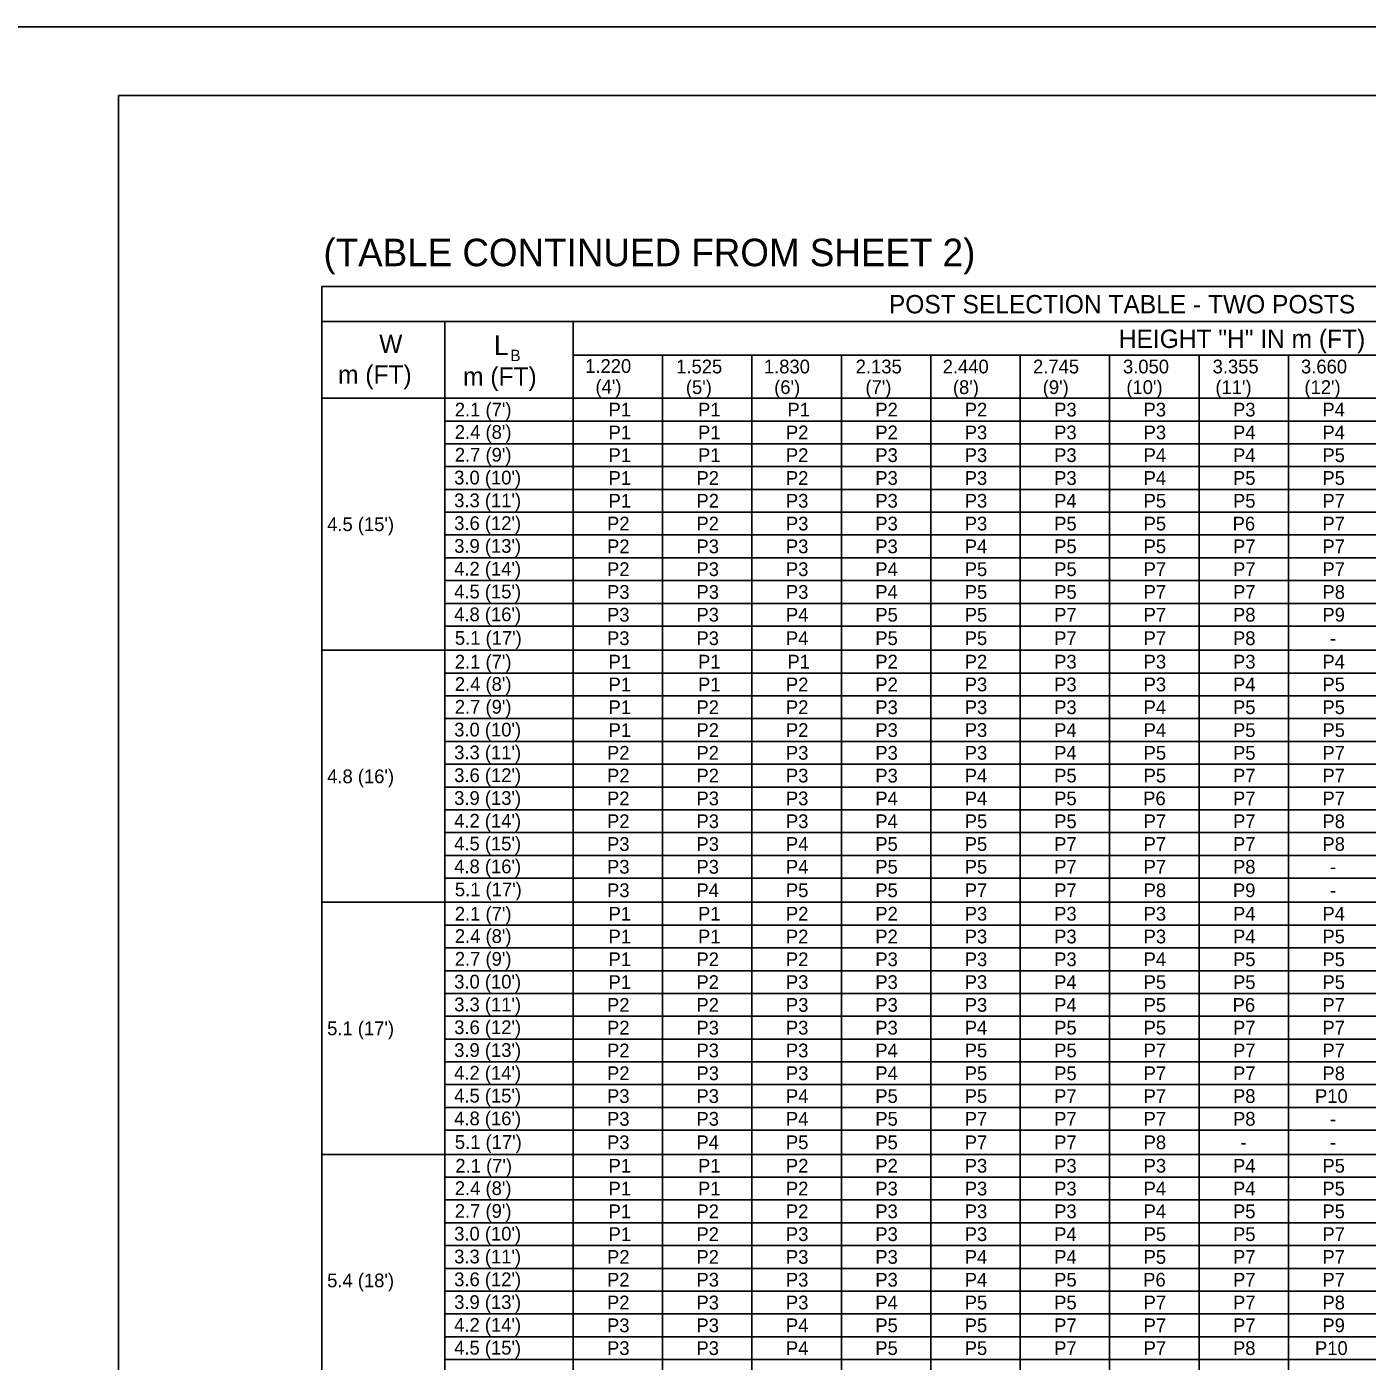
# Model space of a CAD drawing. Extents: x 637580 to 641008, y 294594 to 295782.
# Drawn here: x 639282.3 to 639574.7, y 295490.5 to 295781.6 of the extents above; entities that cross this region are included whole.
import ezdxf

# ---------------------------------------------------------------- set-up
doc = ezdxf.new("R2010")
doc.units = 0
for name, color, linetype in [('1', 7, 'Continuous'), ('2', 7, 'Continuous'), ('3', 7, 'Continuous'), ('PLT-BNDY', 7, 'Continuous')]:
    doc.layers.add(name, color=color, linetype=linetype)

msp = doc.modelspace()

# ---------------------------------------------------------------- linework, layer by layer
at = {"layer": '1'}
for p, q in [((639302.31, 295766.63), (640088.31, 295766.63)), ((639302.31, 295766.63), (639302.31, 295202.63)), ((639346.67, 295724.98), (639713.6, 295724.98)), ((639346.67, 295260.68), (639346.67, 295724.98)), ((639346.67, 295717.3), (639713.6, 295717.3)), ((639373.47, 295260.68), (639373.47, 295717.3)), ((639401.48, 295260.68), (639401.48, 295717.3)), ((639346.67, 295700.6), (639713.6, 295700.6)), ((639346.67, 295645.61), (639713.6, 295645.61)), ((639346.67, 295590.62), (639713.6, 295590.62)), ((639346.67, 295535.63), (639713.6, 295535.63))]:
    msp.add_line(p, q, dxfattribs=at)
at = {"layer": '2'}
for p, q in [((639401.48, 295260.68), (639401.48, 295717.3)), ((639401.48, 295709.96), (639713.6, 295709.96)), ((639420.98, 295260.68), (639420.98, 295709.96)), ((639440.49, 295260.68), (639440.49, 295709.96)), ((639460, 295260.68), (639460, 295709.96)), ((639479.51, 295260.68), (639479.51, 295709.96)), ((639499.01, 295260.68), (639499.01, 295709.96)), ((639518.52, 295260.68), (639518.52, 295709.96)), ((639538.03, 295260.68), (639538.03, 295709.96)), ((639557.54, 295260.68), (639557.54, 295709.96)), ((639373.47, 295695.62), (639713.6, 295695.62)), ((639373.47, 295690.65), (639713.6, 295690.65)), ((639373.47, 295685.68), (639713.6, 295685.68)), ((639373.47, 295680.71), (639713.6, 295680.71)), ((639373.47, 295675.73), (639713.6, 295675.73)), ((639373.47, 295670.76), (639713.6, 295670.76)), ((639373.47, 295665.79), (639713.6, 295665.79)), ((639373.47, 295660.82), (639713.6, 295660.82)), ((639373.47, 295655.84), (639713.6, 295655.84)), ((639373.47, 295650.87), (639713.6, 295650.87)), ((639373.47, 295640.63), (639713.6, 295640.63)), ((639373.47, 295635.66), (639713.6, 295635.66)), ((639373.47, 295630.69), (639713.6, 295630.69)), ((639373.47, 295625.72), (639713.6, 295625.72)), ((639373.47, 295620.74), (639713.6, 295620.74)), ((639373.47, 295615.77), (639713.6, 295615.77)), ((639373.47, 295610.8), (639713.6, 295610.8)), ((639373.47, 295605.83), (639713.6, 295605.83)), ((639373.47, 295600.85), (639713.6, 295600.85)), ((639373.47, 295595.88), (639713.6, 295595.88)), ((639373.47, 295585.64), (639713.6, 295585.64)), ((639373.47, 295580.67), (639713.6, 295580.67)), ((639373.47, 295575.7), (639713.6, 295575.7)), ((639373.47, 295570.73), (639713.6, 295570.73)), ((639373.47, 295565.75), (639713.6, 295565.75)), ((639373.47, 295560.78), (639713.6, 295560.78)), ((639373.47, 295555.81), (639713.6, 295555.81)), ((639373.47, 295550.84), (639713.6, 295550.84)), ((639373.47, 295545.86), (639713.6, 295545.86)), ((639373.47, 295540.89), (639713.6, 295540.89)), ((639373.47, 295530.65), (639713.6, 295530.65)), ((639373.47, 295525.68), (639713.6, 295525.68)), ((639373.47, 295520.71), (639713.6, 295520.71)), ((639373.47, 295515.74), (639713.6, 295515.74)), ((639373.47, 295510.76), (639713.6, 295510.76)), ((639373.47, 295505.79), (639713.6, 295505.79)), ((639373.47, 295500.82), (639713.6, 295500.82)), ((639373.47, 295495.85), (639713.6, 295495.85)), ((639373.47, 295490.87), (639713.6, 295490.87))]:
    msp.add_line(p, q, dxfattribs=at)
at = {"layer": 'PLT-BNDY'}
msp.add_lwpolyline([(639262.31, 295781.63), (640103.31, 295781.63), (640103.31, 295187.63), (639262.31, 295187.63)], close=True, dxfattribs=at)

# ---------------------------------------------------------------- texts
at = {"layer": '1'}
for s, height, p in [('POST SELECTION TABLE - TWO POSTS', 4.003, (639470.37, 295719.11)), ('HEIGHT "H" IN m (FT)', 4.003, (639520.52, 295711.56)), ('W', 4, (639359.19, 295710.47)), ('L', 4.3, (639384.22, 295709.99)), ('B', 2.5, (639387.79, 295708.68)), ('m (FT)', 4.003, (639350.21, 295703.76)), ('m (FT)', 4.003, (639377.48, 295703.36)), ('1.220', 3, (639404.12, 295706.12)), ('1.525', 3, (639423.97, 295706.01)), ('1.830', 3, (639443.1, 295706.01)), ('2.135', 3, (639463.13, 295706.01)), ('2.440', 3, (639482.1, 295706.01)), ('2.745', 3, (639501.81, 295706.01)), ('3.050', 3, (639521.43, 295706.01)), ('3.355', 3, (639540.98, 295706.01)), ('3.660', 3, (639560.27, 295706.01)), ("(4')", 3, (639406.36, 295701.62)), ("(5')", 3, (639426.08, 295701.51)), ("(6')", 3, (639445.34, 295701.51)), ("(7')", 3, (639465.25, 295701.51)), ("(8')", 3, (639484.34, 295701.51)), ("(9')", 3, (639503.93, 295701.51)), ("(10')", 3, (639522.17, 295701.51)), ("(11')", 3, (639541.59, 295701.51)), ("(12')", 3, (639561.01, 295701.51)), ("2.1 (7')", 3, (639375.68, 295696.61)), ('P1', 3, (639409.22, 295696.61)), ('P1', 3, (639428.73, 295696.61)), ('P1', 3, (639448.24, 295696.61)), ('P2', 3, (639467.4, 295696.61)), ('P2', 3, (639486.91, 295696.61)), ('P3', 3, (639506.42, 295696.61)), ('P3', 3, (639525.92, 295696.61)), ('P3', 3, (639545.43, 295696.61)), ('P4', 3, (639564.94, 295696.61)), ("2.4 (8')", 3, (639375.68, 295691.73)), ('P1', 3, (639409.22, 295691.64)), ('P1', 3, (639428.73, 295691.64)), ('P2', 3, (639447.9, 295691.64)), ('P2', 3, (639467.4, 295691.64)), ('P3', 3, (639486.91, 295691.64)), ('P3', 3, (639506.42, 295691.64)), ('P3', 3, (639525.93, 295691.64)), ('P4', 3, (639545.43, 295691.64)), ('P4', 3, (639564.94, 295691.64)), ("2.7 (9')", 3, (639375.68, 295686.76)), ('P1', 3, (639409.22, 295686.67)), ('P1', 3, (639428.73, 295686.67)), ('P2', 3, (639447.9, 295686.67)), ('P3', 3, (639467.4, 295686.67)), ('P3', 3, (639486.91, 295686.67)), ('P3', 3, (639506.42, 295686.67)), ('P4', 3, (639525.93, 295686.67)), ('P4', 3, (639545.43, 295686.67)), ('P5', 3, (639564.94, 295686.67)), ("3.0 (10')", 3, (639375.54, 295681.79)), ('P1', 3, (639409.22, 295681.69)), ('P2', 3, (639428.39, 295681.69)), ('P2', 3, (639447.9, 295681.69)), ('P3', 3, (639467.4, 295681.69)), ('P3', 3, (639486.91, 295681.69)), ('P3', 3, (639506.42, 295681.69)), ('P4', 3, (639525.93, 295681.69)), ('P5', 3, (639545.43, 295681.69)), ('P5', 3, (639564.94, 295681.69)), ("3.3 (11')", 3, (639375.54, 295676.81)), ('P1', 3, (639409.22, 295676.72)), ('P2', 3, (639428.39, 295676.72)), ('P3', 3, (639447.9, 295676.72)), ('P3', 3, (639467.4, 295676.72)), ('P3', 3, (639486.91, 295676.72)), ('P4', 3, (639506.42, 295676.72)), ('P5', 3, (639525.93, 295676.72)), ('P5', 3, (639545.43, 295676.72)), ('P7', 3, (639564.94, 295676.72)), ("3.6 (12')", 3, (639375.54, 295671.84)), ('P2', 3, (639408.88, 295671.75)), ('P2', 3, (639428.39, 295671.75)), ('P3', 3, (639447.9, 295671.75)), ('P3', 3, (639467.4, 295671.75)), ('P3', 3, (639486.91, 295671.75)), ('P6', 3, (639545.35, 295671.75)), ("4.5 (15')", 3, (639347.83, 295671.6)), ('P5', 3, (639506.42, 295671.75)), ('P5', 3, (639525.93, 295671.75)), ('P7', 3, (639564.94, 295671.75)), ("3.9 (13')", 3, (639375.54, 295666.87)), ('P2', 3, (639408.88, 295666.78)), ('P3', 3, (639428.39, 295666.78)), ('P3', 3, (639447.9, 295666.78)), ('P3', 3, (639467.4, 295666.78)), ('P4', 3, (639486.91, 295666.78)), ('P5', 3, (639506.42, 295666.78)), ('P5', 3, (639525.93, 295666.78)), ('P7', 3, (639545.43, 295666.78)), ('P7', 3, (639564.94, 295666.78)), ("4.2 (14')", 3, (639375.54, 295661.9)), ('P2', 3, (639408.88, 295661.8)), ('P3', 3, (639428.39, 295661.8)), ('P3', 3, (639447.9, 295661.8)), ('P4', 3, (639467.4, 295661.8)), ('P5', 3, (639486.91, 295661.8)), ('P5', 3, (639506.42, 295661.8)), ('P7', 3, (639525.93, 295661.8)), ('P7', 3, (639545.43, 295661.8)), ('P7', 3, (639564.94, 295661.8)), ("4.5 (15')", 3, (639375.54, 295656.92)), ('P3', 3, (639408.88, 295656.83)), ('P3', 3, (639428.39, 295656.83)), ('P3', 3, (639447.9, 295656.83)), ('P4', 3, (639467.4, 295656.83)), ('P5', 3, (639486.91, 295656.83)), ('P5', 3, (639506.42, 295656.83)), ('P7', 3, (639525.93, 295656.83)), ('P7', 3, (639545.43, 295656.83)), ('P8', 3, (639564.94, 295656.83)), ("4.8 (16')", 3, (639375.54, 295651.95)), ('P3', 3, (639408.88, 295651.86)), ('P3', 3, (639428.39, 295651.86)), ('P4', 3, (639447.9, 295651.86)), ('P5', 3, (639467.4, 295651.86)), ('P5', 3, (639486.91, 295651.86)), ('P7', 3, (639506.42, 295651.86)), ('P7', 3, (639525.93, 295651.86)), ('P8', 3, (639545.43, 295651.86)), ('P9', 3, (639564.93, 295651.86)), ("5.1 (17')", 3, (639375.69, 295646.8)), ('P3', 3, (639408.88, 295646.74)), ('P3', 3, (639428.39, 295646.74)), ('P4', 3, (639447.9, 295646.74)), ('P5', 3, (639467.4, 295646.74)), ('P5', 3, (639486.91, 295646.74)), ('P7', 3, (639506.42, 295646.74)), ('P7', 3, (639525.93, 295646.74)), ('P8', 3, (639545.43, 295646.74)), ('-', 3, (639566.56, 295646.74)), ("2.1 (7')", 3, (639375.68, 295641.62)), ('P1', 3, (639409.22, 295641.62)), ('P1', 3, (639428.73, 295641.62)), ('P1', 3, (639448.24, 295641.62)), ('P2', 3, (639467.4, 295641.62)), ('P2', 3, (639486.91, 295641.62)), ('P3', 3, (639506.42, 295641.62)), ('P3', 3, (639525.93, 295641.62)), ('P3', 3, (639545.43, 295641.62)), ('P4', 3, (639564.94, 295641.62)), ("2.4 (8')", 3, (639375.68, 295636.74)), ('P2', 3, (639447.9, 295636.65)), ('P2', 3, (639467.4, 295636.65)), ('P3', 3, (639486.91, 295636.65)), ('P3', 3, (639506.42, 295636.65)), ('P3', 3, (639525.93, 295636.65)), ('P1', 3, (639409.22, 295636.65)), ('P1', 3, (639428.73, 295636.65)), ('P4', 3, (639545.43, 295636.65)), ('P5', 3, (639564.94, 295636.65)), ("2.7 (9')", 3, (639375.68, 295631.77)), ('P1', 3, (639409.22, 295631.68)), ('P2', 3, (639428.39, 295631.68)), ('P2', 3, (639447.9, 295631.68)), ('P3', 3, (639467.4, 295631.68)), ('P3', 3, (639486.91, 295631.68)), ('P3', 3, (639506.42, 295631.68)), ('P4', 3, (639525.93, 295631.68)), ('P5', 3, (639545.43, 295631.68)), ('P5', 3, (639564.94, 295631.68)), ("3.0 (10')", 3, (639375.54, 295626.8)), ('P1', 3, (639409.22, 295626.7)), ('P2', 3, (639428.39, 295626.7)), ('P2', 3, (639447.9, 295626.7)), ('P3', 3, (639467.4, 295626.7)), ('P3', 3, (639486.91, 295626.7)), ('P4', 3, (639506.42, 295626.7)), ('P4', 3, (639525.93, 295626.7)), ('P5', 3, (639545.43, 295626.7)), ('P5', 3, (639564.94, 295626.7)), ("3.3 (11')", 3, (639375.54, 295621.82)), ('P2', 3, (639408.88, 295621.73)), ('P2', 3, (639428.39, 295621.73)), ('P3', 3, (639447.9, 295621.73)), ('P3', 3, (639467.4, 295621.73)), ('P3', 3, (639486.91, 295621.73)), ('P4', 3, (639506.42, 295621.73)), ('P5', 3, (639525.93, 295621.73)), ('P5', 3, (639545.43, 295621.73)), ('P7', 3, (639564.94, 295621.73)), ("4.8 (16')", 3, (639347.83, 295616.61)), ("3.6 (12')", 3, (639375.54, 295616.85)), ('P2', 3, (639408.88, 295616.76)), ('P2', 3, (639428.39, 295616.76)), ('P3', 3, (639447.9, 295616.76)), ('P3', 3, (639467.4, 295616.76)), ('P4', 3, (639486.91, 295616.76)), ('P5', 3, (639506.42, 295616.76)), ('P5', 3, (639525.93, 295616.76)), ('P7', 3, (639545.43, 295616.76)), ('P7', 3, (639564.94, 295616.76)), ("3.9 (13')", 3, (639375.54, 295611.88)), ('P2', 3, (639408.88, 295611.79)), ('P3', 3, (639428.39, 295611.79)), ('P3', 3, (639447.9, 295611.79)), ('P4', 3, (639467.4, 295611.79)), ('P4', 3, (639486.91, 295611.79)), ('P5', 3, (639506.42, 295611.79)), ('P6', 3, (639525.84, 295611.79)), ('P7', 3, (639545.43, 295611.79)), ('P7', 3, (639564.94, 295611.79)), ("4.2 (14')", 3, (639375.54, 295606.91)), ('P2', 3, (639408.88, 295606.81)), ('P3', 3, (639428.39, 295606.81)), ('P3', 3, (639447.9, 295606.81)), ('P4', 3, (639467.4, 295606.81)), ('P5', 3, (639486.91, 295606.81)), ('P5', 3, (639506.42, 295606.81)), ('P7', 3, (639525.93, 295606.81)), ('P7', 3, (639545.43, 295606.81)), ('P8', 3, (639564.94, 295606.81)), ("4.5 (15')", 3, (639375.54, 295601.93)), ('P3', 3, (639408.88, 295601.84)), ('P3', 3, (639428.39, 295601.84)), ('P4', 3, (639447.9, 295601.84)), ('P5', 3, (639467.4, 295601.84)), ('P5', 3, (639486.91, 295601.84)), ('P7', 3, (639506.42, 295601.84)), ('P7', 3, (639525.93, 295601.84)), ('P7', 3, (639545.43, 295601.84)), ('P8', 3, (639564.94, 295601.84)), ("4.8 (16')", 3, (639375.54, 295596.96)), ('P3', 3, (639408.88, 295596.87)), ('P3', 3, (639428.39, 295596.87)), ('P4', 3, (639447.9, 295596.87)), ('P5', 3, (639467.4, 295596.87)), ('P5', 3, (639486.91, 295596.87)), ('P7', 3, (639506.42, 295596.87)), ('P7', 3, (639525.93, 295596.87)), ('P8', 3, (639545.43, 295596.87)), ('-', 3, (639566.56, 295596.87)), ("5.1 (17')", 3, (639375.69, 295591.94)), ('P3', 3, (639408.88, 295591.75)), ('P4', 3, (639428.39, 295591.75)), ('P5', 3, (639447.9, 295591.75)), ('P5', 3, (639467.4, 295591.75)), ('P7', 3, (639486.91, 295591.75)), ('P7', 3, (639506.42, 295591.75)), ('P8', 3, (639525.93, 295591.75)), ('P9', 3, (639545.42, 295591.75)), ('-', 3, (639566.56, 295591.75)), ("2.1 (7')", 3, (639375.68, 295586.63)), ('P1', 3, (639409.22, 295586.63)), ('P1', 3, (639428.73, 295586.63)), ('P2', 3, (639447.9, 295586.63)), ('P2', 3, (639467.4, 295586.63)), ('P3', 3, (639486.91, 295586.63)), ('P3', 3, (639506.42, 295586.63)), ('P3', 3, (639525.93, 295586.63)), ('P4', 3, (639545.43, 295586.63)), ('P4', 3, (639564.94, 295586.63)), ("2.4 (8')", 3, (639375.68, 295581.75)), ('P1', 3, (639409.22, 295581.66)), ('P1', 3, (639428.73, 295581.66)), ('P2', 3, (639447.9, 295581.66)), ('P2', 3, (639467.4, 295581.66)), ('P3', 3, (639486.91, 295581.66)), ('P3', 3, (639506.42, 295581.66)), ('P3', 3, (639525.93, 295581.66)), ('P4', 3, (639545.43, 295581.66)), ('P5', 3, (639564.94, 295581.66)), ("2.7 (9')", 3, (639375.68, 295576.78)), ('P1', 3, (639409.22, 295576.69)), ('P2', 3, (639428.39, 295576.69)), ('P2', 3, (639447.9, 295576.69)), ('P3', 3, (639467.4, 295576.69)), ('P3', 3, (639486.91, 295576.69)), ('P3', 3, (639506.42, 295576.69)), ('P4', 3, (639525.93, 295576.69)), ('P5', 3, (639545.43, 295576.69)), ('P5', 3, (639564.94, 295576.69)), ("3.0 (10')", 3, (639375.54, 295571.81)), ('P1', 3, (639409.22, 295571.71)), ('P2', 3, (639428.39, 295571.71)), ('P3', 3, (639447.9, 295571.71)), ('P3', 3, (639467.4, 295571.71)), ('P3', 3, (639486.91, 295571.71)), ('P4', 3, (639506.42, 295571.71)), ('P5', 3, (639525.93, 295571.71)), ('P5', 3, (639545.43, 295571.71)), ('P5', 3, (639564.94, 295571.71)), ("3.3 (11')", 3, (639375.54, 295566.83)), ('P2', 3, (639408.88, 295566.74)), ('P2', 3, (639428.39, 295566.74)), ('P3', 3, (639447.9, 295566.74)), ('P3', 3, (639467.4, 295566.74)), ('P3', 3, (639486.91, 295566.74)), ('P4', 3, (639506.42, 295566.74)), ('P5', 3, (639525.93, 295566.74)), ('P6', 3, (639545.35, 295566.74)), ('P7', 3, (639564.94, 295566.74)), ("5.1 (17')", 3, (639347.83, 295561.62)), ("3.6 (12')", 3, (639375.54, 295561.86)), ('P2', 3, (639408.88, 295561.77)), ('P3', 3, (639428.39, 295561.77)), ('P3', 3, (639447.9, 295561.77)), ('P3', 3, (639467.4, 295561.77)), ('P4', 3, (639486.91, 295561.77)), ('P5', 3, (639506.42, 295561.77)), ('P5', 3, (639525.93, 295561.77)), ('P7', 3, (639545.43, 295561.77)), ('P7', 3, (639564.94, 295561.77)), ("3.9 (13')", 3, (639375.54, 295556.89)), ('P2', 3, (639408.88, 295556.8)), ('P3', 3, (639428.39, 295556.8)), ('P3', 3, (639447.9, 295556.8)), ('P4', 3, (639467.4, 295556.8)), ('P5', 3, (639486.91, 295556.8)), ('P5', 3, (639506.42, 295556.8)), ('P7', 3, (639525.93, 295556.8)), ('P7', 3, (639545.43, 295556.8)), ('P7', 3, (639564.94, 295556.8)), ("4.2 (14')", 3, (639375.54, 295551.92)), ('P2', 3, (639408.88, 295551.82)), ('P3', 3, (639428.39, 295551.82)), ('P3', 3, (639447.9, 295551.82)), ('P4', 3, (639467.4, 295551.82)), ('P5', 3, (639486.91, 295551.82)), ('P5', 3, (639506.42, 295551.82)), ('P7', 3, (639525.93, 295551.82)), ('P7', 3, (639545.43, 295551.82)), ('P8', 3, (639564.94, 295551.82)), ("4.5 (15')", 3, (639375.54, 295546.94)), ('P3', 3, (639408.88, 295546.85)), ('P3', 3, (639428.39, 295546.85)), ('P4', 3, (639447.9, 295546.85)), ('P5', 3, (639467.4, 295546.85)), ('P5', 3, (639486.91, 295546.85)), ('P7', 3, (639506.42, 295546.85)), ('P7', 3, (639525.93, 295546.85)), ('P8', 3, (639545.43, 295546.85)), ('P10', 3, (639563.31, 295546.85)), ("4.8 (16')", 3, (639375.54, 295541.97)), ('P3', 3, (639408.88, 295541.88)), ('P3', 3, (639428.39, 295541.88)), ('P4', 3, (639447.9, 295541.88)), ('P5', 3, (639467.4, 295541.88)), ('P7', 3, (639486.91, 295541.88)), ('P7', 3, (639506.42, 295541.88)), ('P7', 3, (639525.93, 295541.88)), ('P8', 3, (639545.43, 295541.88)), ('-', 3, (639566.56, 295541.88)), ("5.1 (17')", 3, (639375.69, 295536.82)), ('P3', 3, (639408.88, 295536.76)), ('P4', 3, (639428.39, 295536.76)), ('P5', 3, (639447.9, 295536.76)), ('P5', 3, (639467.4, 295536.76)), ('P7', 3, (639486.91, 295536.76)), ('P7', 3, (639506.42, 295536.76)), ('P8', 3, (639525.93, 295536.76)), ('-', 3, (639547.05, 295536.76)), ('-', 3, (639566.56, 295536.76)), ("2.1 (7')", 3, (639375.8, 295531.64)), ('P1', 3, (639409.22, 295531.64)), ('P1', 3, (639428.73, 295531.64)), ('P2', 3, (639447.9, 295531.64)), ('P2', 3, (639467.4, 295531.64)), ('P3', 3, (639486.91, 295531.64)), ('P3', 3, (639506.42, 295531.64)), ('P3', 3, (639525.93, 295531.64)), ('P4', 3, (639545.43, 295531.64)), ('P5', 3, (639564.94, 295531.64)), ("2.4 (8')", 3, (639375.68, 295526.76)), ('P1', 3, (639409.22, 295526.67)), ('P1', 3, (639428.73, 295526.67)), ('P2', 3, (639447.9, 295526.67)), ('P3', 3, (639467.4, 295526.67)), ('P3', 3, (639486.91, 295526.67)), ('P3', 3, (639506.42, 295526.67)), ('P4', 3, (639525.93, 295526.67)), ('P4', 3, (639545.43, 295526.67)), ('P5', 3, (639564.94, 295526.67)), ("2.7 (9')", 3, (639375.68, 295521.79)), ('P1', 3, (639409.22, 295521.7)), ('P2', 3, (639428.39, 295521.7)), ('P2', 3, (639447.9, 295521.7)), ('P3', 3, (639467.4, 295521.7)), ('P3', 3, (639486.91, 295521.7)), ('P3', 3, (639506.42, 295521.7)), ('P4', 3, (639525.93, 295521.7)), ('P5', 3, (639545.43, 295521.7)), ('P5', 3, (639564.94, 295521.7)), ("3.0 (10')", 3, (639375.54, 295516.82)), ('P1', 3, (639409.22, 295516.72)), ('P2', 3, (639428.39, 295516.72)), ('P3', 3, (639447.9, 295516.72)), ('P3', 3, (639467.4, 295516.72)), ('P3', 3, (639486.91, 295516.72)), ('P4', 3, (639506.42, 295516.72)), ('P5', 3, (639525.93, 295516.72)), ('P5', 3, (639545.43, 295516.72)), ('P7', 3, (639564.94, 295516.72)), ("3.3 (11')", 3, (639375.54, 295511.84)), ('P2', 3, (639408.88, 295511.75)), ('P2', 3, (639428.39, 295511.75)), ('P3', 3, (639447.9, 295511.75)), ('P3', 3, (639467.4, 295511.75)), ('P4', 3, (639486.91, 295511.75)), ('P4', 3, (639506.42, 295511.75)), ('P5', 3, (639525.93, 295511.75)), ('P7', 3, (639545.43, 295511.75)), ('P7', 3, (639564.94, 295511.75)), ("5.4 (18')", 3, (639347.83, 295506.63)), ("3.6 (12')", 3, (639375.54, 295506.87)), ('P2', 3, (639408.88, 295506.78)), ('P3', 3, (639428.39, 295506.78)), ('P3', 3, (639447.9, 295506.78)), ('P3', 3, (639467.4, 295506.78)), ('P4', 3, (639486.91, 295506.78)), ('P5', 3, (639506.42, 295506.78)), ('P6', 3, (639525.84, 295506.78)), ('P7', 3, (639545.43, 295506.78)), ('P7', 3, (639564.94, 295506.78)), ("3.9 (13')", 3, (639375.54, 295501.9)), ('P2', 3, (639408.88, 295501.81)), ('P3', 3, (639428.39, 295501.81)), ('P3', 3, (639447.9, 295501.81)), ('P4', 3, (639467.4, 295501.81)), ('P5', 3, (639486.91, 295501.81)), ('P5', 3, (639506.42, 295501.81)), ('P7', 3, (639525.93, 295501.81)), ('P7', 3, (639545.43, 295501.81)), ('P8', 3, (639564.94, 295501.81)), ("4.2 (14')", 3, (639375.54, 295496.93)), ('P3', 3, (639408.88, 295496.83)), ('P3', 3, (639428.39, 295496.83)), ('P4', 3, (639447.9, 295496.83)), ('P5', 3, (639467.4, 295496.83)), ('P5', 3, (639486.91, 295496.83)), ('P7', 3, (639506.42, 295496.83)), ('P7', 3, (639525.93, 295496.83)), ('P7', 3, (639545.43, 295496.83)), ('P9', 3, (639564.93, 295496.83)), ("4.5 (15')", 3, (639375.54, 295491.95)), ('P3', 3, (639408.88, 295491.86)), ('P3', 3, (639428.39, 295491.86)), ('P4', 3, (639447.9, 295491.86)), ('P5', 3, (639467.4, 295491.86)), ('P5', 3, (639486.91, 295491.86)), ('P7', 3, (639506.42, 295491.86)), ('P7', 3, (639525.93, 295491.86)), ('P8', 3, (639545.43, 295491.86)), ('P10', 3, (639563.31, 295491.86))]:
    msp.add_text(s, height=height, dxfattribs=at).set_placement(p)
at = {"layer": '3'}
msp.add_text('(TABLE CONTINUED FROM SHEET 2)', height=6, dxfattribs=at).set_placement((639347.02, 295729.4))

doc.saveas('drawing.dxf')
